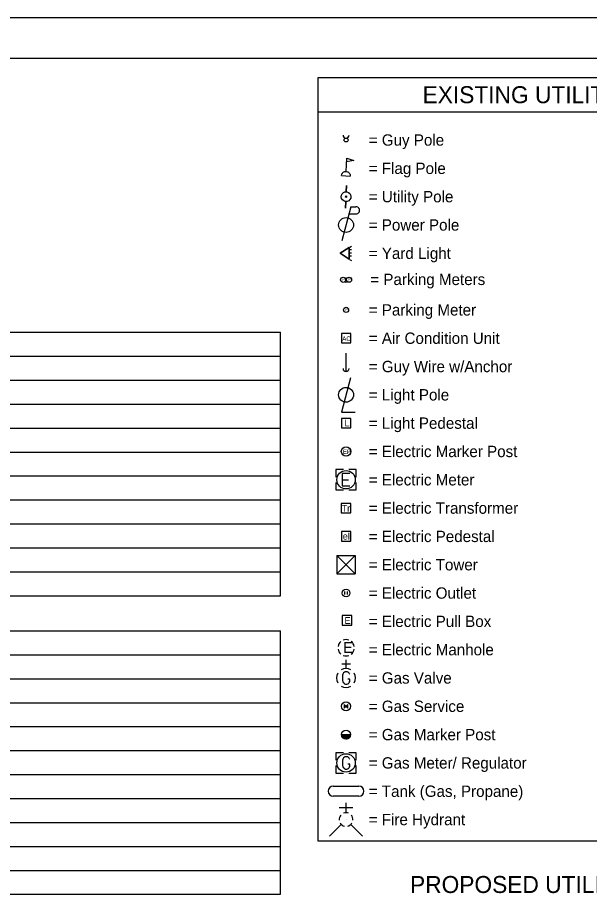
# Model space of a CAD drawing. Extents: x 0 to 34, y 0 to 22.
# Drawn here: x 19.88 to 26.94, y 11.02 to 22 of the extents above; entities that cross this region are included whole.
import ezdxf

# ---------------------------------------------------------------- set-up
doc = ezdxf.new("R2010")
doc.units = 0
for name, color, linetype in [('Default', 7, 'Continuous'), ('SH_Border', 7, 'Continuous'), ('SH_Cut_Line', 7, 'Continuous'), ('SH_Text', 7, 'Continuous'), ('TX_P_5', 7, 'Continuous'), ('UT_X_Electric', 7, 'Continuous')]:
    doc.layers.add(name, color=color, linetype=linetype)

# ---------------------------------------------------------------- blocks, each defined once
blk = doc.blocks.new('POINT_DISPLAY')
at = {"layer": 'Default'}
blk.add_line((0, 0), (0, 0), dxfattribs=at)
blk = doc.blocks.new('lpole')
at = {"layer": 'Default'}
blk.add_lwpolyline([(0.0397, 0.1488), (-0.0397, -0.1528), (0.0794, -0.1528)], dxfattribs=at)
blk.add_circle((0, 0), 0.0655, dxfattribs=at)
blk = doc.blocks.new('1POLE')
at = {"layer": 'Default'}
for points in [[(0, -1), (0, -0.429), (-0.049, -0.426), (-0.19, -0.384), (-0.308, -0.298), (-0.391, -0.176), (-0.427, -0.034), (-0.414, 0.112), (-0.352, 0.245), (-0.248, 0.349), (-0.116, 0.413), (0, 0.429), (0, 1), (0, 0.429), (0.049, 0.426), (0.19, 0.384), (0.308, 0.298), (0.391, 0.176), (0.427, 0.034), (0.414, -0.112), (0.352, -0.245), (0.248, -0.349), (0.116, -0.413), (0, -0.429), (0, -1)], [(0, 0.071), (0.071, 0), (0, -0.071), (-0.071, 0), (0, 0.071)]]:
    blk.add_lwpolyline(points, dxfattribs=at)
blk = doc.blocks.new('ET')
at = {"layer": 'Default'}
for p, q in [((-0.0418, 0.0418), (-0.0418, -0.0418)), ((0.0418, 0.0418), (-0.0418, 0.0418)), ((0.0418, -0.0418), (0.0418, 0.0418)), ((-0.0418, -0.0418), (0.0418, -0.0418))]:
    blk.add_line(p, q, dxfattribs=at)
blk.add_text('E', height=0.06, dxfattribs=at).set_placement((-0.022, -0.0313))
blk = doc.blocks.new('GUYP')
at = {"layer": 'Default'}
blk.add_circle((0, 0), 0.0172, dxfattribs=at)
blk.add_arc((0, 0.0443), 0.0271, 181.48551, 358.51449, dxfattribs=at)
blk = doc.blocks.new('pp')
at = {"layer": 'Default'}
for p, q in [((0.043176, 0.16128), (-0.0378, -0.14112)), ((0.043176, 0.16128), (0.086016, 0.16128)), ((0.025956, 0.09702), (0.086016, 0.09702))]:
    blk.add_line(p, q, dxfattribs=at)
blk.add_circle((0, 0), 0.06552, dxfattribs=at)
blk.add_arc((0.086646, 0.12915), 0.032136, 268.8766972, 91.1233028, dxfattribs=at)
blk = doc.blocks.new('YLGHT')
at = {"layer": 'Default'}
for p, q in [((-0.0521, 0), (0.026, 0.0521)), ((0.026, 0.0521), (0.026, -0.0521)), ((0.0318, 0.0525), (0.0477, 0.0614)), ((0.0318, 0.034), (0.0477, 0.034)), ((0.0318, 0.0034), (0.0477, 0.0034)), ((0.026, -0.0521), (-0.0521, 0)), ((0.0307, -0.0545), (0.0482, -0.0634)), ((0.0318, -0.024), (0.0477, -0.024))]:
    blk.add_line(p, q, dxfattribs=at)
blk.add_lwpolyline([(-0.0521, 0), (0.026, -0.0521), (0.026, -0.0521), (0.026, 0.0521)], close=True, dxfattribs=at)
blk = doc.blocks.new('PMD')
at = {"layer": 'Default'}
for centre, radius in [((-0.0267, 0.0156), 0.0226), ((0, 0), 0.00833), ((0.0259, 0.0165), 0.0226)]:
    blk.add_circle(centre, radius, dxfattribs=at)
for p in [(-0.0316, 0.0058), (0.021, 0.0068)]:
    blk.add_text('P', height=0.0208, rotation=359.804, dxfattribs=at).set_placement(p)
blk = doc.blocks.new('PM')
at = {"layer": 'Default'}
blk.add_circle((0, 0), 0.0226, dxfattribs=at)
blk.add_text('P', height=0.0208, rotation=359.804, dxfattribs=at).set_placement((-0.0049, -0.0097))
blk = doc.blocks.new('GUY')
at = {"layer": 'Default'}
blk.add_line((0, 0), (0, 0.1622), dxfattribs=at)
blk.add_arc((0, 0.0271), 0.0271, 181.48551, 358.51449, dxfattribs=at)
blk = doc.blocks.new('ACU')
at = {"layer": 'Default'}
for p, q in [((0.0418, 0.0418), (-0.0418, 0.0418)), ((-0.0418, 0.0418), (-0.0418, -0.0418)), ((0.0418, -0.0418), (0.0418, 0.0418)), ((-0.0418, -0.0418), (0.0418, -0.0418))]:
    blk.add_line(p, q, dxfattribs=at)
blk.add_text('AC', height=0.03886, dxfattribs=at).set_placement((-0.0337, -0.0231))
blk = doc.blocks.new('LPED')
at = {"layer": 'Default'}
for p, q in [((0.0418, 0.0418), (-0.0418, 0.0418)), ((-0.0418, 0.0418), (-0.0418, -0.0418)), ((0.0418, -0.0418), (0.0418, 0.0418)), ((-0.0418, -0.0418), (0.0418, -0.0418))]:
    blk.add_line(p, q, dxfattribs=at)
blk.add_text('L', height=0.06, dxfattribs=at).set_placement((-0.0142, -0.0283))
blk = doc.blocks.new('ELM')
at = {"layer": 'Default'}
blk.add_circle((0, 0), 0.0421, dxfattribs=at)
blk.add_text('EP', height=0.03748, dxfattribs=at).set_placement((-0.027, -0.0214))
blk = doc.blocks.new('em')
at = {"layer": 'UT_X_Electric'}
blk.add_line((-0.0338, 0), (0.0202, 0), dxfattribs=at)
for points in [[(-0.024, 0.09), (-0.09, 0.09), (-0.09, 0.024)], [(0.09, 0.024), (0.09, 0.09), (0.024, 0.09)], [(0.0337, 0.054), (-0.0338, 0.054), (-0.0338, -0.054), (0.0337, -0.054)], [(-0.09, -0.024), (-0.09, -0.09), (-0.024, -0.09)], [(0.024, -0.09), (0.09, -0.09), (0.09, -0.024)]]:
    blk.add_lwpolyline(points, dxfattribs=at)
blk.add_circle((0, 0), 0.081, dxfattribs=at)
at = {"layer": 'Default'}
blk.add_blockref('POINT_DISPLAY', (0, 0), dxfattribs=at)
blk = doc.blocks.new('ETOWER')
at = {"layer": 'Default'}
for p, q in [((-0.0813, 0.0813), (-0.0813, -0.0813)), ((-0.0813, 0.0813), (0.0813, 0.0813)), ((-0.0813, 0.0813), (0.0813, -0.0813)), ((-0.0813, -0.0813), (0.0813, 0.0813)), ((0.0813, 0.0813), (0.0813, -0.0813)), ((-0.0813, -0.0813), (0.0813, -0.0813))]:
    blk.add_line(p, q, dxfattribs=at)
blk = doc.blocks.new('EPED')
at = {"layer": 'Default'}
for p, q in [((0.0418, 0.0418), (-0.0418, 0.0418)), ((-0.0418, 0.0418), (-0.0418, -0.0418)), ((0.0418, -0.0418), (0.0418, 0.0418)), ((-0.0418, -0.0418), (0.0418, -0.0418))]:
    blk.add_line(p, q, dxfattribs=at)
blk.add_text('el', height=0.05997, dxfattribs=at).set_placement((-0.0291, -0.0289))
blk = doc.blocks.new('EO')
at = {"layer": 'Default'}
for p, q in [((-0.0137, 0.0134), (-0.0137, -0.0133)), ((0.0131, -0.0133), (0.0131, 0.0134))]:
    blk.add_line(p, q, dxfattribs=at)
blk.add_circle((0, 0), 0.0337, dxfattribs=at)
blk = doc.blocks.new('gv')
at = {"layer": 'Default'}
for p, q in [((0, 0.084), (0, 0.1602)), ((0.0382, 0.1221), (-0.0382, 0.1221))]:
    blk.add_line(p, q, dxfattribs=at)
blk.add_lwpolyline([(0.0319, 0.0327), (0.0311, 0.037), (0.0285, 0.0412), (0.0243, 0.0455), (0.0183, 0.0506), (0.0141, 0.0523), (0.0107, 0.0531), (0.0056, 0.054), (-0.0046, 0.054), (-0.0089, 0.0531), (-0.0114, 0.0523), (-0.0148, 0.0506), (-0.0216, 0.0455), (-0.0259, 0.0395), (-0.0284, 0.0327), (-0.0301, 0.0234), (-0.0318, 0.0098), (-0.0318, -0.0081), (-0.031, -0.0225), (-0.0276, -0.0336), (-0.0225, -0.0438), (-0.0182, -0.0472), (-0.0131, -0.0506), (-0.0038, -0.054), (0.0056, -0.054), (0.0149, -0.0523), (0.0183, -0.0506), (0.0217, -0.0489), (0.0251, -0.0455), (0.0285, -0.0404), (0.0319, -0.0327), (0.0319, -0.0115), (0.0141, -0.0115)], dxfattribs=at)
for start, end in [(60.01836, 120.01574), (150.01836, 209.98164), (330.01836, 29.98164), (239.98426, 299.98164)]:
    blk.add_arc((0, 0), 0.084, start, end, dxfattribs=at)
blk = doc.blocks.new('GS')
at = {"layer": 'Default'}
for p, q in [((-0.0164, -0.016), (0.0157, 0.0161)), ((-0.0164, 0.0161), (0.0157, -0.016)), ((-0.0164, 0.0161), (-0.0164, -0.016)), ((0.0157, -0.016), (0.0157, 0.0161))]:
    blk.add_line(p, q, dxfattribs=at)
blk.add_circle((0, 0), 0.0404, dxfattribs=at)
blk = doc.blocks.new('gm')
at = {"layer": 'Default'}
for points in [[(-0.024, 0.09), (-0.09, 0.09), (-0.09, 0.024)], [(0.09, 0.024), (0.09, 0.09), (0.024, 0.09)], [(0.032, 0.0327), (0.0311, 0.037), (0.0286, 0.0412), (0.0243, 0.0455), (0.0184, 0.0506), (0.0141, 0.0523), (0.0107, 0.0531), (0.0056, 0.054), (-0.0046, 0.054), (-0.0088, 0.0531), (-0.0114, 0.0523), (-0.0148, 0.0506), (-0.0216, 0.0455), (-0.0259, 0.0395), (-0.0284, 0.0327), (-0.0301, 0.0234), (-0.0318, 0.0098), (-0.0318, -0.0081), (-0.031, -0.0225), (-0.0276, -0.0336), (-0.0225, -0.0438), (-0.0182, -0.0472), (-0.0131, -0.0506), (-0.0037, -0.054), (0.0056, -0.054), (0.015, -0.0523), (0.0184, -0.0506), (0.0218, -0.0489), (0.0252, -0.0455), (0.0286, -0.0404), (0.032, -0.0327), (0.032, -0.0115), (0.0141, -0.0115)], [(-0.09, -0.024), (-0.09, -0.09), (-0.024, -0.09)], [(0.024, -0.09), (0.09, -0.09), (0.09, -0.024)]]:
    blk.add_lwpolyline(points, dxfattribs=at)
blk.add_circle((0, 0), 0.081, dxfattribs=at)
blk.add_blockref('POINT_DISPLAY', (0, 0), dxfattribs=at)
blk = doc.blocks.new('GLM')
at = {"layer": 'Default'}
for p, q in [((-0.0404, -0.0017), (-0.0378, 0.0009)), ((-0.0404, 0.0001), (-0.0397, 0.0009)), ((-0.0404, 0), (0.0404, 0)), ((-0.0402, -0.0034), (-0.036, 0.0009)), ((-0.04, -0.005), (-0.0342, 0.0009)), ((-0.0397, -0.0066), (-0.0323, 0.0009)), ((-0.0394, -0.0081), (-0.0305, 0.0009)), ((-0.0391, -0.0096), (-0.0286, 0.0009)), ((-0.0387, -0.011), (-0.0268, 0.0009)), ((-0.0382, -0.0124), (-0.025, 0.0009)), ((-0.0377, -0.0137), (-0.0231, 0.0009)), ((-0.0372, -0.015), (-0.0213, 0.0009)), ((-0.0366, -0.0163), (-0.0194, 0.0009)), ((-0.036, -0.0176), (-0.0176, 0.0009)), ((-0.0354, -0.0188), (-0.0158, 0.0009)), ((-0.0347, -0.0199), (-0.0139, 0.0009)), ((-0.034, -0.0211), (-0.0121, 0.0009)), ((-0.0332, -0.0222), (-0.0102, 0.0009)), ((-0.0325, -0.0232), (-0.0084, 0.0009)), ((-0.0317, -0.0243), (-0.0066, 0.0009)), ((-0.0309, -0.0253), (-0.0047, 0.0009)), ((-0.03, -0.0263), (-0.0029, 0.0009)), ((-0.0291, -0.0272), (-0.001, 0.0009)), ((-0.0282, -0.0281), (0.0008, 0.0009)), ((-0.0272, -0.029), (0.0027, 0.0009)), ((-0.0263, -0.0299), (0.0045, 0.0009)), ((-0.0253, -0.0307), (0.0063, 0.0009)), ((-0.0242, -0.0315), (0.0082, 0.0009)), ((-0.0231, -0.0323), (0.01, 0.0009)), ((-0.022, -0.033), (0.0119, 0.0009)), ((-0.0209, -0.0338), (0.0137, 0.0009)), ((-0.0198, -0.0344), (0.0155, 0.0009)), ((-0.0186, -0.0351), (0.0174, 0.0009)), ((-0.0173, -0.0357), (0.0192, 0.0009)), ((-0.0161, -0.0363), (0.0211, 0.0009)), ((-0.0148, -0.0368), (0.0229, 0.0009)), ((-0.0134, -0.0373), (0.0247, 0.0009)), ((-0.012, -0.0378), (0.0266, 0.0009)), ((-0.0106, -0.0382), (0.0284, 0.0009)), ((-0.0091, -0.0385), (0.0303, 0.0009)), ((-0.0076, -0.0389), (0.0321, 0.0009)), ((-0.006, -0.0391), (0.0339, 0.0009)), ((-0.0044, -0.0393), (0.0358, 0.0009)), ((-0.0027, -0.0395), (0.0376, 0.0009)), ((-0.001, -0.0396), (0.0395, 0.0009)), ((0.0009, -0.0396), (0.0404, 0)), ((0.0028, -0.0395), (0.0404, -0.0019)), ((0.0048, -0.0393), (0.0402, -0.004)), ((0.007, -0.039), (0.0398, -0.0061)), ((0.0093, -0.0385), (0.0394, -0.0084)), ((0.0118, -0.0378), (0.0387, -0.011)), ((0.0146, -0.0368), (0.0377, -0.0138)), ((0.0179, -0.0354), (0.0363, -0.0171)), ((0.0222, -0.0329), (0.0338, -0.0214))]:
    blk.add_line(p, q, dxfattribs=at)
blk.add_circle((0, 0), 0.0404, dxfattribs=at)
blk = doc.blocks.new('fh')
at = {"layer": 'Default'}
for p, q in [((0.0599, 0.1032), (-0.0601, 0.1032)), ((-0.0001, 0.0602), (-0.0001, 0.1462)), ((-0.0423, -0.0424), (-0.1463, -0.1463)), ((0.0422, -0.0424), (0.1462, -0.1463))]:
    blk.add_line(p, q, dxfattribs=at)
for start, end in [(140.02099, 184.06293), (68.13946, 112.03798), (356.01648, 39.98885), (211.87877, 255.84793), (283.82389, 329.90967)]:
    blk.add_arc((0, 0), 0.06, start, end, dxfattribs=at)
blk.add_blockref('POINT_DISPLAY', (0, 0), dxfattribs=at)
blk.add_blockref('POINT_DISPLAY', (0, 0), dxfattribs=at)

msp = doc.modelspace()

# ---------------------------------------------------------------- linework, layer by layer
at = {"layer": 'Default'}
for p, q in [((24.031, 20.236), (23.944, 20.219)), ((23.881, 20.049), (23.988, 20.043)), ((23.995, 15.997), (23.878, 15.997)), ((23.878, 15.997), (23.878, 15.88)), ((23.995, 15.88), (23.995, 15.997)), ((23.878, 15.88), (23.995, 15.88)), ((23.779, 12.502), (24.095, 12.502)), ((24.095, 12.376), (23.779, 12.376))]:
    msp.add_line(p, q, dxfattribs=at)
for points in [[(23.937, 20.1), (23.946, 20.266), (24.031, 20.236)], [(23.881, 20.049), (23.881, 20.056), (23.883, 20.063), (23.885, 20.069), (23.889, 20.075), (23.893, 20.081), (23.897, 20.086), (23.902, 20.09), (23.908, 20.094), (23.914, 20.097), (23.921, 20.099), (23.927, 20.1), (23.937, 20.1), (23.954, 20.097), (23.96, 20.094), (23.966, 20.09), (23.971, 20.086), (23.976, 20.081), (23.98, 20.076), (23.983, 20.07), (23.986, 20.064), (23.987, 20.057), (23.988, 20.05), (23.988, 20.043), (23.988, 20.043)]]:
    msp.add_lwpolyline(points, dxfattribs=at)
for centre, radius, start, end in [((23.937, 14.212), 0.101, 130.0806, 170.0721), ((23.937, 14.212), 0.101, 70.0577, 110.1061), ((23.937, 14.212), 0.101, 10.0169, 50.0392), ((23.937, 14.212), 0.101, 190.0169, 230.0392), ((23.937, 14.212), 0.101, 310.0114, 350.0264), ((23.937, 14.212), 0.101, 250.0577, 290.0473), ((23.779, 12.439), 0.0631, 90, 270), ((24.095, 12.439), 0.0631, 270, 90)]:
    msp.add_arc(centre, radius, start, end, dxfattribs=at)
at = {"layer": 'SH_Border'}
msp.add_lwpolyline([(2, 21.5), (33.5, 21.5), (33.5, 0.5), (2, 0.5)], close=True, dxfattribs=at)
at = {"layer": 'SH_Cut_Line'}
msp.add_lwpolyline([(0, 0), (34, 0), (34, 22), (0, 22)], close=True, dxfattribs=at)
at = {"layer": 'SH_Text'}
msp.add_line((23.587, 20.839), (31.729, 20.839), dxfattribs=at)
msp.add_lwpolyline([(23.587, 11.826), (31.729, 11.826), (31.729, 21.259), (23.587, 21.259)], close=True, dxfattribs=at)
at = {"layer": 'TX_P_5'}
for p, q in [((8.165, 18.112), (23.127, 18.112)), ((23.127, 14.856), (23.127, 18.112)), ((8.165, 17.816), (23.127, 17.816)), ((8.165, 17.52), (23.127, 17.52)), ((8.165, 17.224), (23.127, 17.224)), ((8.165, 16.928), (23.127, 16.928)), ((8.165, 16.632), (23.127, 16.632)), ((8.165, 16.336), (23.127, 16.336)), ((8.165, 16.04), (23.127, 16.04)), ((8.165, 15.744), (23.127, 15.744)), ((8.165, 15.448), (23.127, 15.448)), ((8.165, 15.152), (23.127, 15.152)), ((8.165, 14.856), (23.127, 14.856)), ((8.165, 14.421), (23.127, 14.421)), ((23.127, 11.165), (23.127, 14.421)), ((8.165, 14.125), (23.127, 14.125)), ((8.165, 13.829), (23.127, 13.829)), ((8.165, 13.533), (23.127, 13.533)), ((8.165, 13.237), (23.127, 13.237)), ((8.165, 12.941), (23.127, 12.941)), ((8.165, 12.645), (23.127, 12.645)), ((8.165, 12.349), (23.127, 12.349)), ((8.165, 12.053), (23.127, 12.053)), ((8.165, 11.757), (23.127, 11.757)), ((8.165, 11.461), (23.127, 11.461)), ((8.165, 11.165), (23.127, 11.165))]:
    msp.add_line(p, q, dxfattribs=at)

# ---------------------------------------------------------------- block references
at = {"layer": 'Default'}
for name, p, xscale, yscale in [('GUYP', (23.937, 20.489), 1.4000000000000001, 1.4000000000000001), ('pp', (23.937, 19.439), 1.4000000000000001, 1.4000000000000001), ('YLGHT', (23.937, 19.089), 1.4000000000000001, 1.4000000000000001), ('PMD', (23.937, 18.739), 1.4000000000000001, 1.4000000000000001), ('PM', (23.937, 18.389), 1.4000000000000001, 1.4000000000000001), ('ACU', (23.937, 18.039), 1.4000000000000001, 1.4000000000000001), ('GUY', (23.937, 17.627), 1.4000000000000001, 1.4000000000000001), ('lpole', (23.937, 17.339), 1.4000000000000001, 1.4000000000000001), ('LPED', (23.937, 16.989), 1.4000000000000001, 1.4000000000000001), ('ELM', (23.937, 16.639), 1.4000000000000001, 1.4000000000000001), ('em', (23.937, 16.289), 1.4000000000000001, 1.4000000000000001), ('EPED', (23.937, 15.589), 1.4000000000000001, 1.4000000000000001), ('ETOWER', (23.937, 15.239), 1.4000000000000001, 1.4000000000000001), ('EO', (23.937, 14.889), 1.4000000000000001, 1.4000000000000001), ('ET', (23.949, 14.551), 1.4000000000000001, 1.4000000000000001), ('POINT_DISPLAY', (23.937, 14.212), 0.07, 0.07), ('gv', (23.937, 13.839), 1.4000000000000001, 1.4000000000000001), ('GS', (23.937, 13.489), 1.4000000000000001, 1.4000000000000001), ('GLM', (23.937, 13.139), 1.4000000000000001, 1.4000000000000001), ('gm', (23.937, 12.789), 1.4000000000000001, 1.4000000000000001), ('fh', (23.937, 12.089), 1.4000000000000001, 1.4000000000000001)]:
    msp.add_blockref(name, p, dxfattribs=dict(at, xscale=xscale, yscale=yscale))
at = {"layer": 'Default', "xscale": 0.14000000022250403, "yscale": 0.1399999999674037, "rotation": 177.60824376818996}
msp.add_blockref('1POLE', (23.937, 19.788), dxfattribs=at)

# ---------------------------------------------------------------- texts
at = {"layer": 'Default'}
for s, height, p in [('Tr', 0.084, (23.882, 15.895)), ('E', 0.134, (23.901, 14.149))]:
    msp.add_text(s, height=height, dxfattribs=at).set_placement(p)
at = {"layer": 'SH_Text'}
for s, p in [('EXISTING UTILITY SYMBOL LEGEND', (24.882, 20.944)), ('PROPOSED UTILITY SYMBOL LEGEND', (24.727, 11.181))]:
    msp.add_text(s, height=0.21, rotation=0, dxfattribs=at).set_placement(p)
for s, p in [('= Guy Pole', (24.217, 20.419)), ('= Flag Pole', (24.217, 20.069)), ('= Utility Pole', (24.217, 19.719)), ('= Power Pole', (24.217, 19.369)), ('= Yard Light', (24.217, 19.019)), ('= Parking Meters', (24.236, 18.696)), ('= Parking Meter', (24.217, 18.319)), ('= Air Condition Unit', (24.217, 17.969)), ('= Guy Wire w/Anchor', (24.217, 17.619)), ('= Light Pole', (24.217, 17.269)), ('= Light Pedestal', (24.217, 16.919)), ('= Electric Marker Post', (24.217, 16.569)), ('= Electric Meter', (24.217, 16.219)), ('= Electric Transformer', (24.217, 15.869)), ('= Electric Pedestal', (24.217, 15.519)), ('= Electric Tower', (24.217, 15.169)), ('= Electric Outlet', (24.217, 14.819)), ('= Electric Pull Box', (24.217, 14.469)), ('= Electric Manhole', (24.217, 14.119)), ('= Gas Valve', (24.217, 13.769)), ('= Gas Service', (24.217, 13.419)), ('= Gas Marker Post', (24.217, 13.069)), ('= Gas Meter/ Regulator', (24.217, 12.719)), ('= Tank (Gas, Propane)', (24.217, 12.369)), ('= Fire Hydrant', (24.217, 12.019))]:
    msp.add_text(s, height=0.14, dxfattribs=at).set_placement(p)

doc.saveas('drawing.dxf')
